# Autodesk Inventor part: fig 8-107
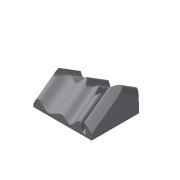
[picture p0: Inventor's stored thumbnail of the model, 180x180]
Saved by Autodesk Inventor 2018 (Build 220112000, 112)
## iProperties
Shininess: 64.0
Length Units: 11269
Angle Units: 11279
Time Units: 11290
Mass Units: 11283
Length Display Precision: 3
Angle Display Precision: 2
Compacted: True
Part Number: fig 8-107
Document SubType Name: Modeling
Created: 2002-12
Designer: deepak
Density: 1 g/cm^3
Material: Generic
Appearance: Default
Density: 0.0
Volumn: 0.0
Area: 0.0
PropertySet Name: Model Information
Control State: 0
Master: False
Checked Out: False
Author: deepak
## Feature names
1. Extrusion1
## Parameters: d1 = 0, d2 = 0, d3 = 0, d4 = 0, d5 = 0
